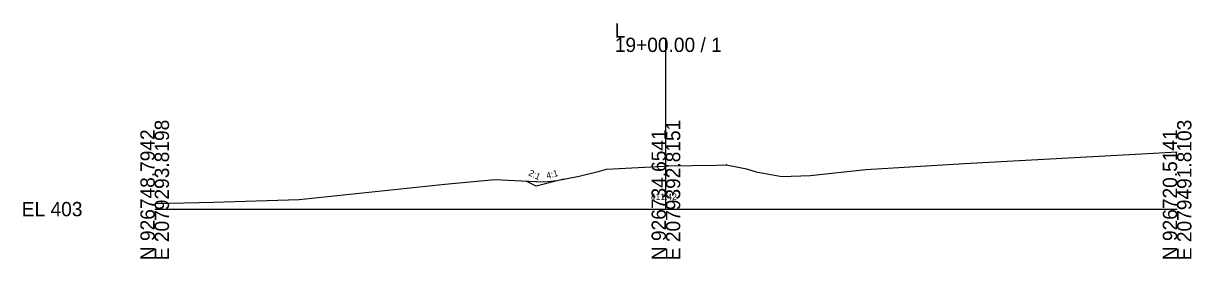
# Model space of a CAD drawing. Extents: x -26 to 10503, y -10 to 9546.
# Drawn here: x 974.3 to 1202.8, y 7990.3 to 8036.3 of the extents above; entities that cross this region are included whole.
import ezdxf

# ---------------------------------------------------------------- set-up
doc = ezdxf.new("R2010")
doc.units = 0
for name, color, linetype in [('Default', 7, 'Continuous'), ('Exist XS Center Line Elevation Label', 7, 'Continuous'), ('Exist XS Ground Line', 7, 'Continuous'), ('Old_Level_63', 7, 'Continuous'), ('Prop XS DDE', 7, 'Continuous'), ('Prop XS Dump Level', 7, 'Continuous'), ('Prop XS Finish Grade', 7, 'Continuous'), ('Prop XS Finish Grade Pavement', 7, 'Continuous'), ('Prop XS Side Slope Text', 7, 'Continuous')]:
    doc.layers.add(name, color=color, linetype=linetype)

msp = doc.modelspace()

# ---------------------------------------------------------------- linework, layer by layer
at = {"layer": 'Default'}
for points in [[(1072.64, 8005.48), (1076.27, 8005.31), (1078.69, 8005.61), (1080, 8005.85), (1074.6, 8004.5)], [(1078.69, 8005.61), (1080, 8005.85), (1074.6, 8004.5), (1072.64, 8005.48), (1076.27, 8005.31)]]:
    msp.add_lwpolyline(points, close=True, dxfattribs=at)
at = {"layer": 'Exist XS Ground Line'}
for p, q in [((1158.4, 8008.89), (1193, 8010.81)), ((1193, 8010.81), (1200, 8011.18)), ((1087.04, 8007.41), (1088.35, 8007.84)), ((1088.35, 8007.84), (1098.26, 8008.35)), ((1098.26, 8008.35), (1100, 8008.42)), ((1100, 8008.42), (1100.48, 8008.45)), ((1100.48, 8008.45), (1109.92, 8008.61)), ((1109.92, 8008.61), (1111.79, 8008.64)), ((1111.79, 8008.64), (1113.47, 8008.31)), ((1113.47, 8008.31), (1115.78, 8007.85)), ((1115.78, 8007.85), (1117.64, 8007.28)), ((1139.12, 8007.74), (1158.4, 8008.89)), ((1056.75, 8004.86), (1066.54, 8005.8)), ((1066.54, 8005.8), (1071.76, 8005.52)), ((1071.76, 8005.52), (1076.27, 8005.31)), ((1076.27, 8005.31), (1078.69, 8005.61)), ((1078.69, 8005.61), (1083.04, 8006.42)), ((1083.04, 8006.42), (1087.04, 8007.41)), ((1117.64, 8007.28), (1122.65, 8006.38)), ((1122.65, 8006.38), (1128.22, 8006.6)), ((1128.22, 8006.6), (1139.12, 8007.74)), ((1028.28, 8001.91), (1056.75, 8004.86)), ((1000, 8001.08), (1011.49, 8001.35)), ((1011.49, 8001.35), (1028.28, 8001.91))]:
    msp.add_line(p, q, dxfattribs=at)
at = {"layer": 'Old_Level_63'}
for p, q in [((1100, 8000), (1100, 8033.54)), ((1000, 8000), (1100, 8000)), ((1100, 8000), (1200, 8000))]:
    msp.add_line(p, q, dxfattribs=at)
at = {"layer": 'Prop XS DDE'}
for p, q in [((1080, 8005.85), (1074.6, 8004.5)), ((1074.6, 8004.5), (1072.64, 8005.48))]:
    msp.add_line(p, q, dxfattribs=at)
at = {"layer": 'Prop XS Finish Grade'}
msp.add_line((1100, 8000), (1100, 8000), dxfattribs=at)
at = {"layer": 'Prop XS Finish Grade Pavement'}
for p, q in [((1100, 8008.52), (1100.47, 8008.54)), ((1111.79, 8008.74), (1111.83, 8008.74)), ((1111.83, 8008.74), (1111.9, 8008.74))]:
    msp.add_line(p, q, dxfattribs=at)

# ---------------------------------------------------------------- texts
at = {"layer": 'Exist XS Center Line Elevation Label'}
msp.add_text('411.42', height=1.25, rotation=360, dxfattribs=at).set_placement((1097.04, 8001.8))
at = {"layer": 'Old_Level_63'}
for s, p in [('L', (1090, 8033.54)), ('19+00.00 / 1', (1090, 8030.74)), ('EL 403', (974, 7998.6))]:
    msp.add_text(s, height=2.8, dxfattribs=at).set_placement(p)
for s, p in [('E 2079293.8198', (1002.8, 7990)), ('E 2079392.8151', (1102.8, 7990)), ('E 2079491.8103', (1202.8, 7990)), ('N 926748.7942', (1000, 7990)), ('N 926734.6541', (1100, 7990)), ('N 926720.5141', (1200, 7990))]:
    msp.add_text(s, height=2.8, rotation=90, dxfattribs=at).set_placement(p)
at = {"layer": 'Prop XS Dump Level'}
msp.add_text('Case1', height=0.04, dxfattribs=at).set_placement((1119.87, 8008.29))
at = {"layer": 'Prop XS Side Slope Text'}
for s, rotation, p in [('2:1', 333.4349, (1072.99, 8006.69)), ('4:1', 15.4834, (1076.78, 8005.89))]:
    msp.add_text(s, height=1.25, rotation=rotation, dxfattribs=at).set_placement(p)

doc.saveas('drawing.dxf')
